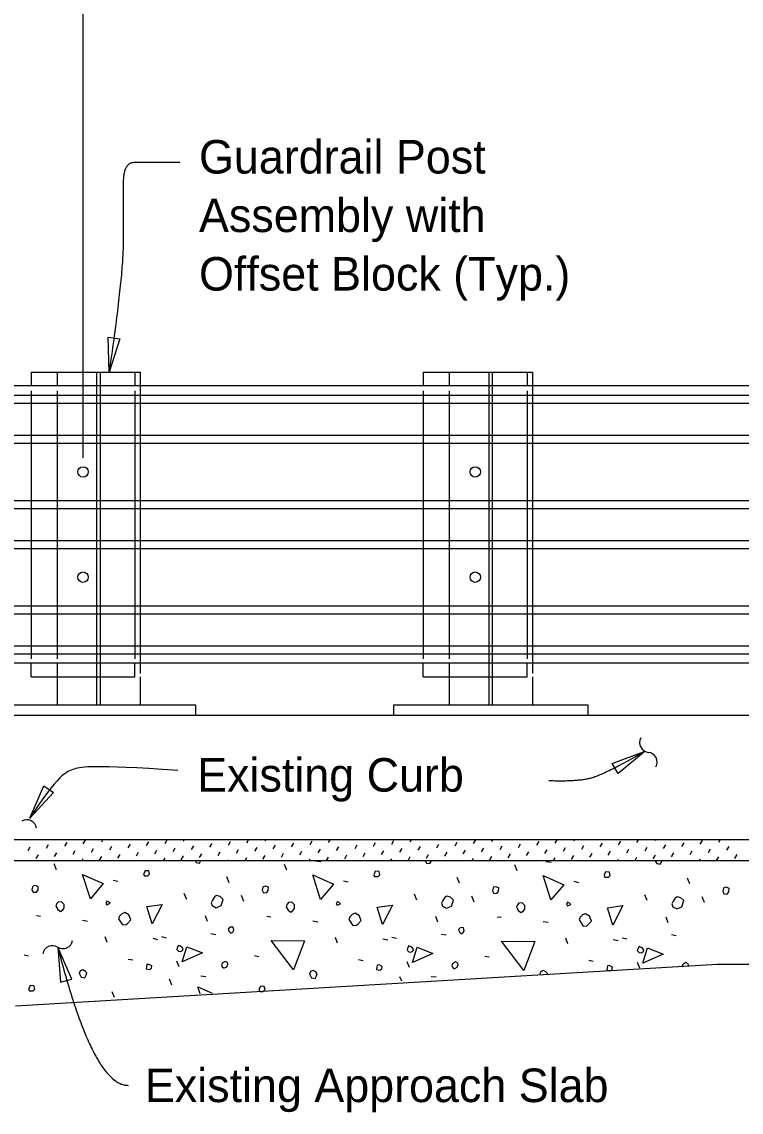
# Model space of a CAD drawing. Extents: x 21587 to 21659.1, y 56113.9 to 56155.9.
# Drawn here: x 21595 to 21599.32, y 56132.41 to 56138.97 of the extents above; entities that cross this region are included whole.
import ezdxf

# ---------------------------------------------------------------- set-up
doc = ezdxf.new("R2010")
doc.units = 0
for name, color, linetype in [('AdhocPoint_dp', 7, 'Continuous'), ('Border', 7, 'Continuous'), ('Patterning', 7, 'Continuous'), ('PlotBorder_dp', 7, 'Continuous'), ('SheetBorder_dp', 7, 'Continuous'), ('TextMisc', 7, 'Continuous')]:
    doc.layers.add(name, color=color, linetype=linetype)

msp = doc.modelspace()

# ---------------------------------------------------------------- linework, layer by layer
at = {"layer": 'AdhocPoint_dp'}
for p, q in [((21593.9596, 56134.8009), (21601.9067, 56134.8009)), ((21604.323, 56134.0511), (21593.9596, 56134.0511)), ((21593.9596, 56133.926), (21604.323, 56133.926)), ((21599.1795, 56133.301), (21594.9596, 56133.051)), ((21604.323, 56133.301), (21599.1795, 56133.301))]:
    msp.add_line(p, q, dxfattribs=at)
at = {"layer": 'Border'}
for p, q in [((21595.2096, 56136.8635), (21595.7096, 56136.8635)), ((21595.2096, 56136.8635), (21595.2096, 56136.7802)), ((21597.5677, 56136.8635), (21598.0677, 56136.8635)), ((21597.5677, 56136.8635), (21597.5677, 56136.7802)), ((21599.7592, 56136.7801), (21587.6633, 56136.7801)), ((21587.6633, 56136.7246), (21599.7592, 56136.7246)), ((21587.6633, 56136.6764), (21599.7592, 56136.6764)), ((21587.6633, 56136.4835), (21599.7592, 56136.4835)), ((21587.6633, 56136.4353), (21599.7592, 56136.4353)), ((21587.6633, 56136.0914), (21599.7592, 56136.0914)), ((21587.6633, 56136.0431), (21599.7592, 56136.0431)), ((21587.6633, 56135.8503), (21599.7592, 56135.8503)), ((21587.6633, 56135.8022), (21599.7592, 56135.8022)), ((21587.6633, 56135.4582), (21599.7592, 56135.4582)), ((21587.6633, 56135.41), (21599.7592, 56135.41)), ((21587.6633, 56135.2172), (21599.7592, 56135.2172)), ((21587.6633, 56135.169), (21599.7592, 56135.169)), ((21599.7592, 56135.1134), (21587.6633, 56135.1134)), ((21595.2096, 56135.1135), (21595.2096, 56134.8635)), ((21597.5677, 56135.1135), (21597.5677, 56134.8635)), ((21595.7096, 56135.0302), (21595.7096, 56134.8635)), ((21598.0677, 56135.0302), (21598.0677, 56134.8635)), ((21594.8762, 56134.8635), (21596.0429, 56134.8635)), ((21595.2096, 56134.8635), (21595.7096, 56134.8635)), ((21596.0429, 56134.8635), (21596.0429, 56134.801)), ((21597.2344, 56134.8635), (21598.401, 56134.8635)), ((21597.2344, 56134.801), (21597.2344, 56134.8635)), ((21597.5677, 56134.8635), (21598.0677, 56134.8635)), ((21598.401, 56134.8635), (21598.401, 56134.801)), ((21594.8762, 56134.801), (21596.0429, 56134.801)), ((21597.2344, 56134.801), (21598.401, 56134.801))]:
    msp.add_line(p, q, dxfattribs=at)
for centre in [(21595.3658, 56136.2634), (21597.724, 56136.2634), (21595.3658, 56135.6303), (21597.724, 56135.6303)]:
    msp.add_circle(centre, 0.0312, dxfattribs=at)
at = {"layer": 'Patterning'}
for p, q in [((21595.4491, 56134.8635), (21595.4491, 56136.8635)), ((21595.47, 56134.8635), (21595.47, 56136.8635)), ((21595.7096, 56136.8635), (21595.7096, 56135.0505)), ((21597.8073, 56134.8635), (21597.8073, 56136.8635)), ((21597.8281, 56134.8635), (21597.8281, 56136.8635)), ((21598.0677, 56136.8635), (21598.0677, 56135.0505)), ((21595.2096, 56136.7516), (21595.2096, 56135.1398)), ((21597.5677, 56136.7516), (21597.5677, 56135.1398))]:
    msp.add_line(p, q, dxfattribs=at)
at = {"layer": 'PlotBorder_dp'}
msp.add_line((21595.3658, 56136.3484), (21595.3658, 56141.1869), dxfattribs=at)
for points in [[(21595.5221, 56136.8635), (21595.5179, 56137.0747), (21595.5877, 56137.0643)], [(21598.7452, 56134.5845), (21598.5825, 56134.4497), (21598.5472, 56134.5108)], [(21595.0458, 56134.1809), (21595.13, 56134.3747), (21595.1891, 56134.3361)], [(21595.2137, 56133.4055), (21595.2308, 56133.1949), (21595.2992, 56133.2123)]]:
    msp.add_lwpolyline(points, close=True, dxfattribs=at)
for centre, start, end in [((21598.7718, 56134.636), 151.52667, 263.25389), ((21598.7578, 56134.5176), 331.52667, 83.25389), ((21595.0274, 56134.1118), 7.95358, 119.6808), ((21595.1822, 56133.3544), 58.43842, 170.16564), ((21595.2447, 56133.456), 238.43842, 350.16564)]:
    msp.add_arc(centre, 0.0596, start, end, dxfattribs=at)
for points, degree in [([(21595.947, 56138.1237), (21595.7421, 56138.1237), (21595.6078, 56138.1237), (21595.6078, 56137.8833), (21595.6078, 56137.4378), (21595.5221, 56136.8635)], 2), ([(21598.1653, 56134.4076), (21598.3174, 56134.4019), (21598.4885, 56134.4362), (21598.7452, 56134.5845)], 2), ([(21595.9359, 56134.4685), (21595.4144, 56134.5022), (21595.311, 56134.48), (21595.217, 56134.4435), (21595.0459, 56134.181)], 3), ([(21595.2142, 56133.4054), (21595.4254, 56132.5742), (21595.6366, 56132.5742)], 2)]:
    msp.add_open_spline(points, degree=degree, dxfattribs=at)
at = {"layer": 'TextMisc'}
for p, q in [((21595.0533, 56136.8635), (21595.6783, 56136.8635)), ((21595.0533, 56136.8635), (21595.0533, 56136.7802)), ((21595.6783, 56136.8635), (21595.6783, 56136.7802)), ((21597.4115, 56136.8635), (21598.0365, 56136.8635)), ((21597.4115, 56136.8635), (21597.4115, 56136.7802)), ((21598.0365, 56136.8635), (21598.0365, 56136.7802)), ((21595.0533, 56136.7516), (21595.0533, 56135.1398)), ((21595.6783, 56136.7516), (21595.6783, 56135.1398)), ((21597.4115, 56136.7516), (21597.4115, 56135.1398)), ((21598.0365, 56136.7516), (21598.0365, 56135.1398)), ((21595.0533, 56135.0302), (21595.0533, 56135.1135)), ((21595.6783, 56135.0302), (21595.6783, 56135.1135)), ((21597.4115, 56135.0302), (21597.4115, 56135.1135)), ((21598.0365, 56135.0302), (21598.0365, 56135.1135)), ((21595.0533, 56135.0302), (21595.6783, 56135.0302)), ((21597.4115, 56135.0302), (21598.0365, 56135.0302)), ((21595.0355, 56133.9869), (21595.0485, 56134.0093)), ((21595.0973, 56134.0487), (21595.0987, 56134.0511)), ((21595.1462, 56133.9999), (21595.1591, 56134.0223)), ((21595.2568, 56134.0129), (21595.2697, 56134.0353)), ((21595.3674, 56134.0258), (21595.3804, 56134.0482)), ((21595.4163, 56133.977), (21595.4292, 56133.9994)), ((21595.478, 56134.0388), (21595.4852, 56134.0511)), ((21595.5269, 56133.99), (21595.5398, 56134.0124)), ((21595.6375, 56134.0029), (21595.6505, 56134.0253)), ((21595.7481, 56134.0159), (21595.7611, 56134.0383)), ((21595.8588, 56134.0289), (21595.8717, 56134.0511)), ((21595.9076, 56133.98), (21595.9206, 56134.0024)), ((21595.9694, 56134.0418), (21595.9748, 56134.0511)), ((21596.0182, 56133.993), (21596.0312, 56134.0154)), ((21596.1289, 56134.0059), (21596.1418, 56134.0283)), ((21596.2395, 56134.0189), (21596.2525, 56134.0413)), ((21596.3501, 56134.0319), (21596.3613, 56134.0511)), ((21596.399, 56133.983), (21596.4119, 56134.0054)), ((21596.4608, 56134.0448), (21596.4644, 56134.0511)), ((21596.5096, 56133.996), (21596.5226, 56134.0184)), ((21596.6202, 56134.009), (21596.6332, 56134.0314)), ((21596.7309, 56134.0219), (21596.7438, 56134.0443)), ((21596.8415, 56134.0349), (21596.8509, 56134.0511)), ((21596.8903, 56133.9861), (21596.9033, 56134.0084)), ((21596.9521, 56134.0479), (21596.954, 56134.0511)), ((21597.001, 56133.999), (21597.0139, 56134.0214)), ((21597.1116, 56134.012), (21597.1246, 56134.0344)), ((21597.2222, 56134.0249), (21597.2352, 56134.0473)), ((21597.2711, 56133.9761), (21597.284, 56133.9985)), ((21597.3329, 56134.0379), (21597.3405, 56134.0511)), ((21597.3817, 56133.9891), (21597.3947, 56134.0115)), ((21597.4435, 56134.0509), (21597.4436, 56134.0511)), ((21597.4923, 56134.002), (21597.5053, 56134.0244)), ((21597.603, 56134.015), (21597.6159, 56134.0374)), ((21597.7136, 56134.028), (21597.7266, 56134.0504)), ((21597.7624, 56133.9791), (21597.7754, 56134.0015)), ((21597.8242, 56134.0409), (21597.8301, 56134.0511)), ((21597.8731, 56133.9921), (21597.886, 56134.0145)), ((21597.9837, 56134.0051), (21597.9967, 56134.0275)), ((21598.0943, 56134.018), (21598.1073, 56134.0404)), ((21598.205, 56134.031), (21598.2166, 56134.0511)), ((21598.2538, 56133.9822), (21598.2668, 56134.0045)), ((21598.3156, 56134.044), (21598.3197, 56134.0511)), ((21598.3644, 56133.9951), (21598.3774, 56134.0175)), ((21598.4751, 56134.0081), (21598.488, 56134.0305)), ((21598.5857, 56134.021), (21598.5987, 56134.0434)), ((21598.6963, 56134.034), (21598.7062, 56134.0511)), ((21598.7452, 56133.9852), (21598.7581, 56134.0076)), ((21598.807, 56134.047), (21598.8094, 56134.0511)), ((21598.8558, 56133.9981), (21598.8688, 56134.0205)), ((21598.9664, 56134.0111), (21598.9794, 56134.0335)), ((21599.0771, 56134.0241), (21599.09, 56134.0465)), ((21599.1259, 56133.9752), (21599.1389, 56133.9976)), ((21599.1877, 56134.037), (21599.1958, 56134.0511)), ((21599.2365, 56133.9882), (21599.2495, 56134.0106)), ((21599.2983, 56134.05), (21599.299, 56134.0511)), ((21595.0844, 56133.9381), (21595.0973, 56133.9605)), ((21595.195, 56133.9511), (21595.2079, 56133.9735)), ((21595.3056, 56133.964), (21595.3186, 56133.9864)), ((21595.3607, 56133.926), (21595.3674, 56133.9376)), ((21595.4651, 56133.9282), (21595.478, 56133.9506)), ((21595.5757, 56133.9411), (21595.5887, 56133.9635)), ((21595.6864, 56133.9541), (21595.6993, 56133.9765)), ((21595.797, 56133.9671), (21595.8099, 56133.9894)), ((21595.8503, 56133.926), (21595.8588, 56133.9406)), ((21595.9565, 56133.9312), (21595.9694, 56133.9536)), ((21596.0671, 56133.9441), (21596.08, 56133.9665)), ((21596.1777, 56133.9571), (21596.1907, 56133.9795)), ((21596.2368, 56133.926), (21596.2395, 56133.9307)), ((21596.2883, 56133.9701), (21596.3013, 56133.9925)), ((21596.34, 56133.926), (21596.3501, 56133.9436)), ((21596.4478, 56133.9342), (21596.4608, 56133.9566)), ((21596.5584, 56133.9472), (21596.5714, 56133.9696)), ((21596.6691, 56133.9601), (21596.682, 56133.9825)), ((21596.7264, 56133.926), (21596.7309, 56133.9337)), ((21596.7797, 56133.9731), (21596.7927, 56133.9955)), ((21596.8296, 56133.926), (21596.8415, 56133.9466)), ((21596.9392, 56133.9372), (21596.9521, 56133.9596)), ((21597.0498, 56133.9502), (21597.0628, 56133.9726)), ((21597.1604, 56133.9631), (21597.1734, 56133.9855)), ((21597.2161, 56133.926), (21597.2222, 56133.9367)), ((21597.3199, 56133.9273), (21597.3329, 56133.9497)), ((21597.4305, 56133.9402), (21597.4435, 56133.9626)), ((21597.5412, 56133.9532), (21597.5541, 56133.9756)), ((21597.6518, 56133.9662), (21597.6648, 56133.9886)), ((21597.7057, 56133.926), (21597.7136, 56133.9397)), ((21597.8113, 56133.9303), (21597.8242, 56133.9527)), ((21597.9219, 56133.9433), (21597.9349, 56133.9657)), ((21598.0325, 56133.9562), (21598.0455, 56133.9786)), ((21598.1432, 56133.9692), (21598.1561, 56133.9916)), ((21598.1953, 56133.926), (21598.205, 56133.9427)), ((21598.3026, 56133.9333), (21598.3156, 56133.9557)), ((21598.4133, 56133.9463), (21598.4262, 56133.9687)), ((21598.5239, 56133.9592), (21598.5369, 56133.9816)), ((21598.5818, 56133.926), (21598.5857, 56133.9328)), ((21598.6345, 56133.9722), (21598.6475, 56133.9946)), ((21598.6849, 56133.926), (21598.6963, 56133.9458)), ((21598.794, 56133.9363), (21598.807, 56133.9587)), ((21598.9046, 56133.9493), (21598.9176, 56133.9717)), ((21599.0153, 56133.9623), (21599.0282, 56133.9847)), ((21599.0714, 56133.926), (21599.0771, 56133.9358)), ((21599.1747, 56133.9264), (21599.1877, 56133.9488)), ((21599.2854, 56133.9394), (21599.2983, 56133.9617)), ((21595.2066, 56133.8712), (21595.1924, 56133.9065)), ((21595.3891, 56133.926), (21595.411, 56133.9236)), ((21595.7472, 56133.926), (21595.7481, 56133.9276)), ((21596.5913, 56133.8676), (21596.5771, 56133.903)), ((21596.7639, 56133.9236), (21596.7957, 56133.9201)), ((21597.6025, 56133.926), (21597.603, 56133.9268)), ((21597.9759, 56133.8641), (21597.9618, 56133.8995)), ((21598.0922, 56133.926), (21598.0943, 56133.9298)), ((21598.1485, 56133.9201), (21598.1804, 56133.9165)), ((21595.5471, 56133.8087), (21595.5754, 56133.8016)), ((21596.2454, 56133.7928), (21596.2313, 56133.8281)), ((21596.9318, 56133.8051), (21596.9601, 56133.7981)), ((21597.6301, 56133.7892), (21597.6159, 56133.8246)), ((21598.3165, 56133.8016), (21598.3448, 56133.7945)), ((21599.0148, 56133.7857), (21599.0006, 56133.8211)), ((21595.9891, 56133.692), (21595.9749, 56133.7274)), ((21596.3332, 56133.6803), (21596.319, 56133.7156)), ((21597.3737, 56133.6885), (21597.3596, 56133.7238)), ((21597.7178, 56133.6767), (21597.7037, 56133.7121)), ((21598.7584, 56133.6849), (21598.7443, 56133.7203)), ((21599.1025, 56133.6732), (21599.0884, 56133.7085)), ((21595.0864, 56133.5954), (21595.1111, 56133.5919)), ((21595.3621, 56133.5671), (21595.3922, 56133.5618)), ((21596.1146, 56133.5594), (21596.1022, 56133.593)), ((21596.471, 56133.5919), (21596.4958, 56133.5883)), ((21596.7468, 56133.5636), (21596.7769, 56133.5583)), ((21597.4993, 56133.5559), (21597.4869, 56133.5895)), ((21597.8557, 56133.5883), (21597.8805, 56133.5848)), ((21598.1315, 56133.5601), (21598.1615, 56133.5547)), ((21598.8839, 56133.5524), (21598.8716, 56133.5859)), ((21596.1334, 56133.4876), (21596.1635, 56133.4823)), ((21597.5181, 56133.484), (21597.5481, 56133.4787)), ((21598.9028, 56133.4805), (21598.9328, 56133.4752)), ((21595.5106, 56133.4328), (21595.4983, 56133.4664)), ((21595.7846, 56133.4593), (21595.8129, 56133.4522)), ((21595.837, 56133.4693), (21595.8653, 56133.4622)), ((21596.8953, 56133.4292), (21596.8829, 56133.4628)), ((21597.1693, 56133.4558), (21597.1976, 56133.4487)), ((21597.2217, 56133.4657), (21597.25, 56133.4587)), ((21598.28, 56133.4257), (21598.2676, 56133.4593)), ((21598.554, 56133.4522), (21598.5823, 56133.4451)), ((21598.6064, 56133.4622), (21598.6347, 56133.4551)), ((21595.0121, 56133.3585), (21595.0386, 56133.3532)), ((21596.3968, 56133.355), (21596.4233, 56133.3497)), ((21597.7815, 56133.3515), (21597.808, 56133.3462)), ((21595.6379, 56133.3338), (21595.6644, 56133.3285)), ((21595.9431, 56133.2867), (21595.9307, 56133.3203)), ((21597.0226, 56133.3302), (21597.0491, 56133.3249)), ((21597.3278, 56133.2831), (21597.3154, 56133.3167)), ((21598.4073, 56133.3267), (21598.4338, 56133.3214)), ((21598.7125, 56133.2796), (21598.7001, 56133.3132)), ((21595.9007, 56133.1771), (21595.8865, 56133.2124)), ((21596.0733, 56133.233), (21596.1051, 56133.2295)), ((21597.2818, 56133.2001), (21597.2712, 56133.2267)), ((21597.458, 56133.2295), (21597.4898, 56133.2259)), ((21595.5548, 56133.1022), (21595.5407, 56133.1376))]:
    msp.add_line(p, q, dxfattribs=at)
for points in [[(21595.7345, 56133.8334), (21595.7557, 56133.8334), (21595.7663, 56133.844), (21595.761, 56133.8635), (21595.738, 56133.8653), (21595.7345, 56133.8546), (21595.7292, 56133.8458), (21595.7345, 56133.8334), (21595.731, 56133.837)], [(21596.0394, 56133.926), (21596.0456, 56133.9147), (21596.0669, 56133.9112), (21596.0751, 56133.926)], [(21597.4221, 56133.926), (21597.4303, 56133.9112), (21597.4515, 56133.9077), (21597.4604, 56133.9236), (21597.461, 56133.926)], [(21598.8049, 56133.926), (21598.8062, 56133.9236)], [(21598.8062, 56133.9236), (21598.815, 56133.9077), (21598.8362, 56133.9041), (21598.845, 56133.9201), (21598.8465, 56133.926)], [(21595.4099, 56133.6962), (21595.3621, 56133.8429), (21595.4877, 56133.7881), (21595.4099, 56133.6962)], [(21596.7945, 56133.6926), (21596.7468, 56133.8394), (21596.8723, 56133.7846), (21596.7945, 56133.6926)], [(21597.1192, 56133.8299), (21597.1404, 56133.8299), (21597.151, 56133.8405), (21597.1457, 56133.8599), (21597.1227, 56133.8617), (21597.1192, 56133.8511), (21597.1139, 56133.8423), (21597.1192, 56133.8299), (21597.1157, 56133.8334)], [(21598.1792, 56133.6891), (21598.1315, 56133.8358), (21598.257, 56133.781), (21598.1792, 56133.6891)], [(21598.5039, 56133.8264), (21598.5251, 56133.8264), (21598.5357, 56133.837), (21598.5304, 56133.8564), (21598.5074, 56133.8582), (21598.5039, 56133.8476), (21598.4986, 56133.8387), (21598.5039, 56133.8264), (21598.5003, 56133.8299)], [(21595.0581, 56133.751), (21595.0669, 56133.7351), (21595.0864, 56133.7368), (21595.0952, 56133.7492), (21595.097, 56133.7686), (21595.0846, 56133.774), (21595.0758, 56133.7757), (21595.0652, 56133.7722), (21595.0616, 56133.7686), (21595.0581, 56133.751)], [(21596.4428, 56133.7474), (21596.4516, 56133.7315), (21596.471, 56133.7333), (21596.4799, 56133.7457), (21596.4817, 56133.7651), (21596.4693, 56133.7704), (21596.4604, 56133.7722), (21596.4498, 56133.7686), (21596.4463, 56133.7651), (21596.4428, 56133.7474)], [(21597.8274, 56133.7439), (21597.8363, 56133.728), (21597.8557, 56133.7298), (21597.8646, 56133.7421), (21597.8663, 56133.7616), (21597.854, 56133.7669), (21597.8451, 56133.7686), (21597.8345, 56133.7651), (21597.831, 56133.7616), (21597.8274, 56133.7439)], [(21599.2121, 56133.7404), (21599.221, 56133.7245), (21599.2404, 56133.7262), (21599.2492, 56133.7386), (21599.251, 56133.758), (21599.2386, 56133.7633), (21599.2298, 56133.7651), (21599.2192, 56133.7616), (21599.2156, 56133.758), (21599.2121, 56133.7404)], [(21595.203, 56133.652), (21595.2136, 56133.6308), (21595.2313, 56133.6202), (21595.2455, 56133.6308), (21595.2525, 56133.6414), (21595.2525, 56133.6626), (21595.2366, 56133.6785), (21595.2172, 56133.6767), (21595.2083, 56133.6679), (21595.203, 56133.652)], [(21595.5089, 56133.6608), (21595.5283, 56133.6697), (21595.5212, 56133.6767), (21595.5089, 56133.682), (21595.5036, 56133.6697), (21595.5089, 56133.6608)], [(21596.1429, 56133.6549), (21596.1658, 56133.6425), (21596.1959, 56133.6549), (21596.2083, 56133.692), (21596.1906, 56133.7097), (21596.1676, 56133.715), (21596.157, 56133.7079), (21596.1446, 56133.6885), (21596.1358, 56133.6726), (21596.1429, 56133.6549)], [(21596.5877, 56133.6484), (21596.5983, 56133.6272), (21596.616, 56133.6166), (21596.6301, 56133.6272), (21596.6372, 56133.6378), (21596.6372, 56133.659), (21596.6213, 56133.675), (21596.6019, 56133.6732), (21596.593, 56133.6644), (21596.5877, 56133.6484)], [(21596.8935, 56133.6573), (21596.913, 56133.6661), (21596.9059, 56133.6732), (21596.8935, 56133.6785), (21596.8882, 56133.6661), (21596.8935, 56133.6573)], [(21597.5275, 56133.6514), (21597.5505, 56133.639), (21597.5806, 56133.6514), (21597.593, 56133.6885), (21597.5753, 56133.7062), (21597.5523, 56133.7115), (21597.5417, 56133.7044), (21597.5293, 56133.6849), (21597.5205, 56133.669), (21597.5275, 56133.6514)], [(21597.9724, 56133.6449), (21597.983, 56133.6237), (21598.0007, 56133.6131), (21598.0148, 56133.6237), (21598.0219, 56133.6343), (21598.0219, 56133.6555), (21598.006, 56133.6714), (21597.9865, 56133.6697), (21597.9777, 56133.6608), (21597.9724, 56133.6449)], [(21598.2782, 56133.6537), (21598.2977, 56133.6626), (21598.2906, 56133.6697), (21598.2782, 56133.675), (21598.2729, 56133.6626), (21598.2782, 56133.6537)], [(21598.9122, 56133.6478), (21598.9352, 56133.6354), (21598.9653, 56133.6478), (21598.9776, 56133.6849), (21598.9599, 56133.7026), (21598.937, 56133.7079), (21598.9264, 56133.7008), (21598.914, 56133.6814), (21598.9051, 56133.6655), (21598.9122, 56133.6478)], [(21595.5796, 56133.576), (21595.6026, 56133.5388), (21595.6255, 56133.5406), (21595.6344, 56133.5494), (21595.6538, 56133.5689), (21595.6414, 56133.5989), (21595.6167, 56133.6131), (21595.599, 56133.606), (21595.5849, 56133.5919), (21595.5796, 56133.576)], [(21595.7822, 56133.5453), (21595.7487, 56133.6496), (21595.8423, 56133.662), (21595.7822, 56133.5453)], [(21596.9643, 56133.5724), (21596.9872, 56133.5353), (21597.0102, 56133.5371), (21597.0191, 56133.5459), (21597.0385, 56133.5654), (21597.0261, 56133.5954), (21597.0014, 56133.6096), (21596.9837, 56133.6025), (21596.9696, 56133.5883), (21596.9643, 56133.5724)], [(21597.1669, 56133.5417), (21597.1333, 56133.646), (21597.227, 56133.6584), (21597.1669, 56133.5417)], [(21598.3489, 56133.5689), (21598.3719, 56133.5318), (21598.3949, 56133.5335), (21598.4037, 56133.5424), (21598.4232, 56133.5618), (21598.4108, 56133.5919), (21598.3861, 56133.606), (21598.3684, 56133.5989), (21598.3542, 56133.5848), (21598.3489, 56133.5689)], [(21598.5516, 56133.5382), (21598.518, 56133.6425), (21598.6117, 56133.6549), (21598.5516, 56133.5382)], [(21596.2448, 56133.4999), (21596.2554, 56133.4893), (21596.266, 56133.4964), (21596.2731, 56133.507), (21596.2695, 56133.5247), (21596.2607, 56133.5265), (21596.2483, 56133.5247), (21596.2377, 56133.5141), (21596.2448, 56133.4999)], [(21597.6294, 56133.4964), (21597.6401, 56133.4858), (21597.6507, 56133.4929), (21597.6577, 56133.5035), (21597.6542, 56133.5212), (21597.6454, 56133.5229), (21597.633, 56133.5212), (21597.6224, 56133.5106), (21597.6294, 56133.4964)], [(21595.9396, 56133.3809), (21595.9519, 56133.3791), (21595.9643, 56133.3844), (21595.9679, 56133.395), (21595.9626, 56133.4039), (21595.9519, 56133.4109), (21595.9396, 56133.4162), (21595.9325, 56133.4021), (21595.929, 56133.3915), (21595.9396, 56133.3809)], [(21595.9619, 56133.3161), (21595.9902, 56133.408), (21596.0839, 56133.3709), (21595.9619, 56133.3161)], [(21596.6319, 56133.2684), (21596.4976, 56133.4451), (21596.6973, 56133.4434), (21596.6319, 56133.2684)], [(21597.3242, 56133.3773), (21597.3366, 56133.3756), (21597.349, 56133.3809), (21597.3525, 56133.3915), (21597.3472, 56133.4003), (21597.3366, 56133.4074), (21597.3242, 56133.4127), (21597.3172, 56133.3986), (21597.3136, 56133.388), (21597.3242, 56133.3773)], [(21598.0166, 56133.2648), (21597.8822, 56133.4416), (21598.082, 56133.4398), (21598.0166, 56133.2648)], [(21598.7089, 56133.3738), (21598.7213, 56133.372), (21598.7337, 56133.3773), (21598.7372, 56133.388), (21598.7319, 56133.3968), (21598.7213, 56133.4039), (21598.7089, 56133.4092), (21598.7019, 56133.395), (21598.6983, 56133.3844), (21598.7089, 56133.3738)], [(21597.3466, 56133.3126), (21597.3749, 56133.4045), (21597.4686, 56133.3674), (21597.3466, 56133.3126)], [(21598.7313, 56133.309), (21598.7596, 56133.401), (21598.8533, 56133.3638), (21598.7313, 56133.309)], [(21595.7457, 56133.2754), (21595.7652, 56133.2701), (21595.7776, 56133.279), (21595.7793, 56133.2914), (21595.7758, 56133.2949), (21595.7617, 56133.302), (21595.7493, 56133.3002), (21595.7475, 56133.2878), (21595.7457, 56133.2754)], [(21596.2094, 56133.2807), (21596.2165, 56133.2807), (21596.2306, 56133.2878), (21596.2359, 56133.3037), (21596.2342, 56133.3126), (21596.22, 56133.3196), (21596.2023, 56133.309), (21596.1988, 56133.2984), (21596.2023, 56133.2878), (21596.2094, 56133.2807)], [(21597.1304, 56133.2719), (21597.1499, 56133.2666), (21597.1622, 56133.2754), (21597.164, 56133.2878), (21597.1605, 56133.2914), (21597.1463, 56133.2984), (21597.134, 56133.2967), (21597.1322, 56133.2843), (21597.1304, 56133.2719)], [(21597.5941, 56133.2772), (21597.6012, 56133.2772), (21597.6153, 56133.2843), (21597.6206, 56133.3002), (21597.6188, 56133.309), (21597.6047, 56133.3161), (21597.587, 56133.3055), (21597.5835, 56133.2949), (21597.587, 56133.2843), (21597.5941, 56133.2772)], [(21598.5151, 56133.2684), (21598.5345, 56133.2631), (21598.5469, 56133.2719), (21598.5487, 56133.2843), (21598.5452, 56133.2878), (21598.531, 56133.2949), (21598.5186, 56133.2931), (21598.5169, 56133.2807), (21598.5151, 56133.2684)], [(21599.003, 56133.2899), (21599.0053, 56133.2967), (21599.0035, 56133.3055), (21598.9894, 56133.3126), (21598.9717, 56133.302), (21598.9682, 56133.2914), (21598.9693, 56133.2878)], [(21595.3462, 56133.2401), (21595.3551, 56133.2242), (21595.3763, 56133.2206), (21595.3851, 56133.2366), (21595.3887, 56133.2507), (21595.3798, 56133.2595), (21595.3639, 56133.2684), (21595.348, 56133.2631), (21595.3427, 56133.2472), (21595.3462, 56133.2401)], [(21596.7309, 56133.2366), (21596.7397, 56133.2206), (21596.761, 56133.2171), (21596.7698, 56133.233), (21596.7733, 56133.2472), (21596.7645, 56133.256), (21596.7486, 56133.2648), (21596.7327, 56133.2595), (21596.7274, 56133.2436), (21596.7309, 56133.2366)], [(21598.1564, 56133.2405), (21598.158, 56133.2471), (21598.1492, 56133.256), (21598.1333, 56133.2648), (21598.1174, 56133.2595), (21598.112, 56133.2436), (21598.1149, 56133.2379)], [(21595.0439, 56133.1429), (21595.0652, 56133.1429), (21595.0758, 56133.1535), (21595.0705, 56133.1729), (21595.0475, 56133.1747), (21595.0439, 56133.1641), (21595.0386, 56133.1552), (21595.0439, 56133.1429), (21595.0404, 56133.1464)], [(21596.07, 56133.1238), (21596.0562, 56133.1659), (21596.1425, 56133.1283)], [(21596.4286, 56133.1393), (21596.4498, 56133.1393), (21596.4604, 56133.1499), (21596.4551, 56133.1694), (21596.4322, 56133.1711), (21596.4286, 56133.1605), (21596.4233, 56133.1517), (21596.4286, 56133.1393), (21596.4251, 56133.1429)]]:
    msp.add_lwpolyline(points, dxfattribs=at)

# ---------------------------------------------------------------- texts
at = {"layer": 'PlotBorder_dp'}
for s, p in [('Guardrail Post ', (21596.0633, 56138.0579)), ('Assembly with ', (21596.0633, 56137.7059)), ('Offset Block (Typ.)', (21596.0633, 56137.3539))]:
    msp.add_text(s, height=0.2016, dxfattribs=at).set_placement(p)
at = {"layer": 'SheetBorder_dp'}
for s, p in [('Existing Curb', (21596.0521, 56134.3406)), ('Existing Approach Slab', (21595.7377, 56132.4736))]:
    msp.add_text(s, height=0.2016, dxfattribs=at).set_placement(p)

doc.saveas('drawing.dxf')
